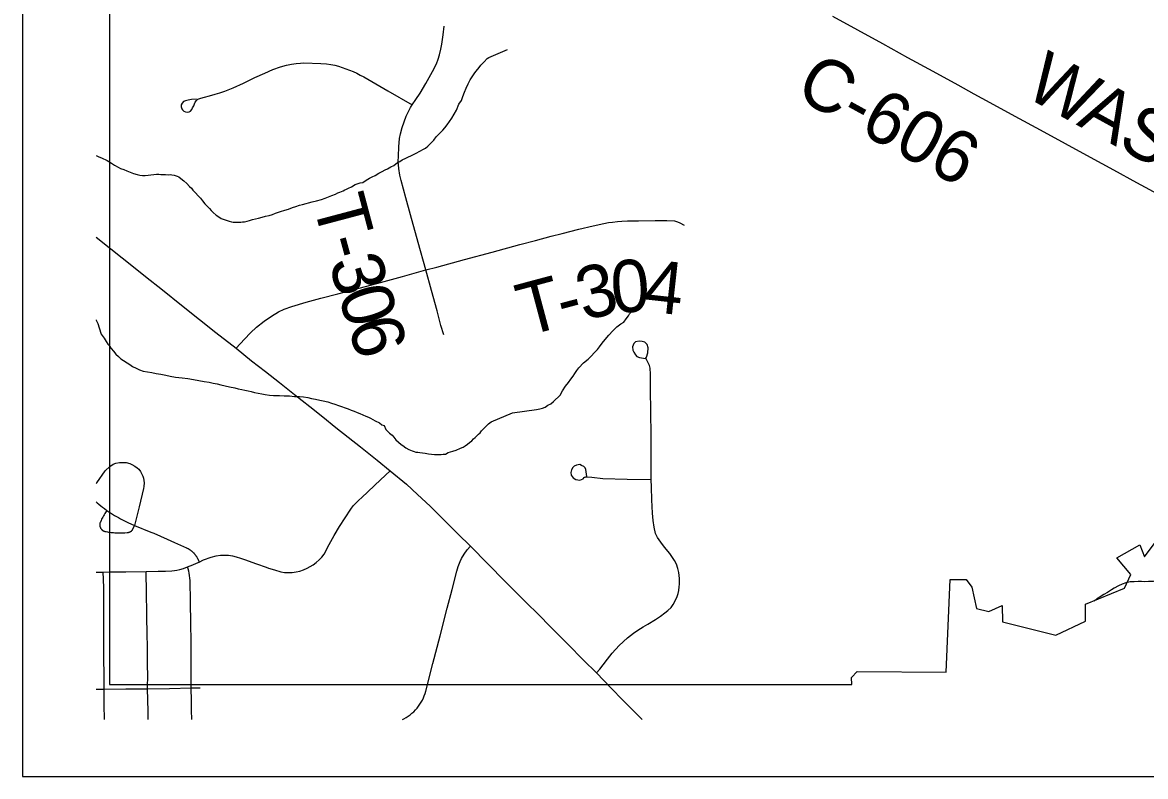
# Model space of a CAD drawing. Extents: x -11.4 to 84.1, y 11.1 to 59.
# Drawn here: x 26.165 to 27.387, y 40.548 to 41.368 of the extents above; entities that cross this region are included whole.
import ezdxf

# ---------------------------------------------------------------- set-up
doc = ezdxf.new("R2010")
doc.units = 0
for name, color, linetype in [('GM_X_Corporation', 7, 'Continuous'), ('GM_X_County_Road', 7, 'Continuous'), ('GM_X_County_Road_Text', 7, 'Continuous'), ('GM_X_Minor_River', 7, 'Continuous'), ('GM_X_Township_Road', 7, 'Continuous'), ('GM_X_Township_Road_Text', 7, 'Continuous'), ('SH_Data', 7, 'Continuous')]:
    doc.layers.add(name, color=color, linetype=linetype)

msp = doc.modelspace()

# ---------------------------------------------------------------- linework, layer by layer
at = {"layer": 'GM_X_Corporation'}
for points in [[(26.2599, 41.4853), (26.2599, 40.6483), (27.0672, 40.6483)], [(27.0672, 40.6483), (27.067, 40.6559), (27.0731, 40.6623), (27.1697, 40.6617), (27.1741, 40.7625), (27.1917, 40.7624), (27.1979, 40.754), (27.2027, 40.731), (27.2161, 40.7278), (27.2309, 40.7343), (27.2311, 40.7163), (27.2892, 40.702), (27.3213, 40.7172), (27.3213, 40.7356), (27.3639, 40.7528), (27.3708, 40.768), (27.3554, 40.7859), (27.3805, 40.7999), (27.3856, 40.7872), (27.4014, 40.8083)]]:
    msp.add_lwpolyline(points, dxfattribs=at)
at = {"layer": 'GM_X_County_Road'}
for points in [[(27.0462, 41.3747), (27.0735, 41.3597), (27.1007, 41.3448), (27.1279, 41.3298), (27.1552, 41.3149), (27.1824, 41.2999), (27.1999, 41.2903), (27.2174, 41.2807), (27.2446, 41.2659), (27.2719, 41.251), (27.2992, 41.2362), (27.3265, 41.2213), (27.3518, 41.2076), (27.377, 41.1938)], [(27.377, 41.1938), (27.4043, 41.179), (27.4259, 41.1672), (27.4474, 41.1555)], [(26.2454, 41.1344), (26.2615, 41.1216), (26.2859, 41.1023), (26.3009, 41.0904), (26.3159, 41.0785), (26.3402, 41.0592), (26.358, 41.045), (26.3757, 41.0308), (26.3976, 41.0137), (26.4143, 41.0002), (26.4295, 40.9884), (26.4447, 40.9766), (26.4612, 40.9635), (26.4777, 40.9505), (26.4919, 40.9391), (26.5061, 40.9277), (26.5195, 40.9171), (26.533, 40.9064), (26.551, 40.892), (26.565, 40.8805), (26.5831, 40.8659), (26.595, 40.8549), (26.6088, 40.842), (26.6238, 40.827), (26.6387, 40.812), (26.6525, 40.7986), (26.6714, 40.7795), (26.6902, 40.7604), (26.7016, 40.7489), (26.7131, 40.7375), (26.7264, 40.7242), (26.7396, 40.7109), (26.7583, 40.6921), (26.7754, 40.6749), (26.7894, 40.6609), (26.805, 40.6447), (26.8187, 40.631), (26.8325, 40.6172), (26.8394, 40.6103)]]:
    msp.add_lwpolyline(points, dxfattribs=at)
at = {"layer": 'GM_X_Minor_River'}
for points in [[(26.6479, 41.2965), (26.65, 41.3011), (26.6522, 41.3054), (26.6544, 41.3088), (26.6567, 41.3119), (26.6585, 41.3146), (26.6604, 41.3169), (26.6618, 41.3189), (26.6637, 41.3212), (26.6655, 41.3231), (26.6674, 41.3251), (26.6708, 41.3286), (26.6726, 41.3298), (26.6928, 41.3384)], [(26.3409, 41.1955), (26.344, 41.1929), (26.3471, 41.1895), (26.349, 41.1876), (26.3506, 41.1854), (26.3529, 41.1835), (26.3572, 41.1787), (26.3588, 41.1768), (26.3611, 41.1738), (26.3635, 41.1708), (26.3662, 41.1682), (26.3686, 41.1656), (26.3705, 41.1633), (26.3728, 41.1611), (26.3759, 41.1585), (26.379, 41.1566), (26.3814, 41.1548), (26.3837, 41.1541), (26.3856, 41.1533), (26.3879, 41.1526), (26.3902, 41.1519), (26.3925, 41.1512), (26.3944, 41.1509), (26.3967, 41.1509), (26.3986, 41.1506), (26.4005, 41.1506), (26.4028, 41.1506), (26.4047, 41.1511), (26.4066, 41.1511), (26.4096, 41.1519), (26.4123, 41.1527), (26.4153, 41.1536), (26.4187, 41.1544), (26.4221, 41.1552), (26.4259, 41.1561), (26.4297, 41.1573), (26.4335, 41.1581), (26.4372, 41.159), (26.4406, 41.1606), (26.4459, 41.1622), (26.4505, 41.1638), (26.4546, 41.165), (26.4588, 41.1666), (26.4626, 41.1679), (26.4664, 41.1691), (26.4698, 41.1699), (26.4804, 41.1728), (26.4849, 41.174), (26.4906, 41.1753), (26.4944, 41.1769), (26.4981, 41.1781), (26.5019, 41.1797), (26.5057, 41.1813), (26.5083, 41.1825), (26.5106, 41.1833), (26.514, 41.1849), (26.5159, 41.1857), (26.5178, 41.1865), (26.52, 41.1877), (26.523, 41.1893), (26.5272, 41.1916), (26.5325, 41.1933), (26.5355, 41.1937), (26.5392, 41.1964), (26.5426, 41.1984), (26.5456, 41.2), (26.5487, 41.2016), (26.5528, 41.204), (26.5566, 41.2059), (26.5599, 41.2075), (26.5622, 41.2087), (26.5641, 41.2099), (26.566, 41.2107), (26.569, 41.2123), (26.5731, 41.2154), (26.5757, 41.2166), (26.5784, 41.2186), (26.5821, 41.2202), (26.5851, 41.2217), (26.5878, 41.2229), (26.5904, 41.2241), (26.5927, 41.2253), (26.598, 41.2281), (26.6006, 41.2297), (26.6036, 41.2313), (26.6062, 41.2332), (26.6088, 41.2359), (26.6126, 41.2398), (26.6151, 41.2433), (26.6226, 41.2507), (26.6248, 41.2534), (26.627, 41.2565), (26.6296, 41.26), (26.6322, 41.2638), (26.6348, 41.2681), (26.6373, 41.2723), (26.6399, 41.2788), (26.6428, 41.2831), (26.6443, 41.2873), (26.6461, 41.2919), (26.6479, 41.2965)], [(26.2454, 41.2231), (26.2462, 41.2229), (26.2485, 41.2218), (26.2512, 41.2207), (26.2535, 41.2196), (26.2554, 41.2189), (26.2573, 41.2178), (26.2593, 41.2166), (26.262, 41.2148), (26.2654, 41.2126), (26.2693, 41.2104), (26.272, 41.2089), (26.2755, 41.2078), (26.2789, 41.2064), (26.2824, 41.2049), (26.2862, 41.2035), (26.29, 41.2024), (26.2931, 41.2017), (26.2958, 41.2014), (26.2988, 41.2015), (26.3019, 41.2019), (26.3049, 41.2023), (26.3083, 41.2024), (26.311, 41.2028), (26.3136, 41.2029), (26.3159, 41.2026), (26.3186, 41.2026), (26.3209, 41.2027), (26.3236, 41.2023), (26.3258, 41.2024), (26.3278, 41.202), (26.3301, 41.2017), (26.3335, 41.2006), (26.3354, 41.1999), (26.3377, 41.1981), (26.3409, 41.1955)], [(26.6984, 40.9436), (26.7245, 40.9473), (26.7279, 40.9477), (26.7309, 40.9485), (26.7339, 40.9497), (26.7365, 40.9517), (26.7399, 40.9532), (26.7429, 40.956), (26.75, 40.9629), (26.7526, 40.9675), (26.7559, 40.9725), (26.7593, 40.9764), (26.7615, 40.9802), (26.7641, 40.9833), (26.766, 40.9864), (26.7682, 40.9895), (26.7704, 40.9925), (26.7756, 40.9979), (26.7805, 41.0018), (26.7843, 41.0053), (26.7872, 41.0088), (26.7906, 41.0123), (26.7928, 41.0153), (26.7958, 41.0192), (26.7991, 41.0234), (26.8029, 41.028), (26.8073, 41.0327), (26.8118, 41.0369), (26.8159, 41.0404), (26.8193, 41.042), (26.8219, 41.0455), (26.8245, 41.0489), (26.8256, 41.0512), (26.8269, 41.0525)], [(26.2454, 41.0447), (26.2456, 41.0443), (26.2472, 41.0405), (26.2488, 41.0359), (26.2508, 41.0291), (26.254, 41.0246), (26.2564, 41.0209), (26.2583, 41.0182), (26.2603, 41.016), (26.2619, 41.0134), (26.2642, 41.0104), (26.2669, 41.0074), (26.2697, 41.0048), (26.2724, 41.0022), (26.282, 40.9959), (26.2851, 40.994), (26.289, 40.9922), (26.2925, 40.9904), (26.2967, 40.9889), (26.3013, 40.9879), (26.3059, 40.9872), (26.3108, 40.9862), (26.3158, 40.9855), (26.3211, 40.9845), (26.3261, 40.9835), (26.3319, 40.9824), (26.3391, 40.9814), (26.3452, 40.9808), (26.3513, 40.9798), (26.3571, 40.9788), (26.3628, 40.9777), (26.3682, 40.9767), (26.3728, 40.9756), (26.377, 40.975), (26.3812, 40.9739), (26.3858, 40.9729), (26.3904, 40.9718), (26.3961, 40.9708), (26.3999, 40.9697), (26.4038, 40.969), (26.4072, 40.9683), (26.4106, 40.9673), (26.4141, 40.9666), (26.4175, 40.9655), (26.4217, 40.9648), (26.4256, 40.9641), (26.4294, 40.9635), (26.434, 40.9628), (26.4382, 40.9625), (26.4447, 40.9623), (26.45, 40.962), (26.4557, 40.9621), (26.461, 40.9614), (26.4664, 40.9612), (26.471, 40.9609), (26.4755, 40.9602), (26.4798, 40.9592), (26.484, 40.9585), (26.4886, 40.9574), (26.4924, 40.9567), (26.4974, 40.9553), (26.5012, 40.9539), (26.505, 40.9528), (26.5089, 40.9514), (26.5196, 40.9478), (26.5227, 40.9463), (26.5261, 40.9453), (26.5292, 40.9438), (26.5323, 40.9427), (26.5354, 40.9412), (26.5388, 40.9398), (26.5415, 40.9387)], [(26.5415, 40.9387), (26.5438, 40.9376), (26.5465, 40.9361), (26.5488, 40.935), (26.5535, 40.9325), (26.5562, 40.9306), (26.5585, 40.9299), (26.5605, 40.9254), (26.5644, 40.9213), (26.5675, 40.9191), (26.569, 40.9172), (26.5714, 40.9142), (26.5772, 40.909), (26.5791, 40.9079), (26.5822, 40.9056), (26.5853, 40.9038), (26.5872, 40.9031), (26.5892, 40.9024), (26.5911, 40.9016), (26.593, 40.9009), (26.5953, 40.9006), (26.5976, 40.9003), (26.6003, 40.8999), (26.6033, 40.8996), (26.6068, 40.8989), (26.6102, 40.8986), (26.6133, 40.8983), (26.6159, 40.8983), (26.6186, 40.8984), (26.6205, 40.8984), (26.6228, 40.8985), (26.6254, 40.8985), (26.6284, 40.9005), (26.6334, 40.9017), (26.6371, 40.903), (26.6417, 40.905), (26.6447, 40.9062), (26.6469, 40.9077), (26.6492, 40.9093), (26.6514, 40.9112), (26.6541, 40.9132), (26.6559, 40.9151), (26.6578, 40.9167), (26.6611, 40.9202), (26.663, 40.9218), (26.6645, 40.9241), (26.6671, 40.9264), (26.6697, 40.9291), (26.6723, 40.9315), (26.6749, 40.9338), (26.6984, 40.9436)], [(27.4173, 40.7632), (27.4135, 40.7628), (27.409, 40.7619), (27.4014, 40.7607), (27.3953, 40.7602), (27.39, 40.7601), (27.3858, 40.76), (27.3824, 40.7604), (27.3786, 40.7603), (27.3744, 40.7599), (27.3699, 40.7598), (27.3653, 40.7589), (27.3612, 40.7574), (27.3574, 40.7554), (27.3525, 40.753), (27.3495, 40.7511), (27.3454, 40.7483), (27.3412, 40.746), (27.3375, 40.7437), (27.3341, 40.7417), (27.3322, 40.7401), (27.3303, 40.739), (27.3303, 40.739)]]:
    msp.add_lwpolyline(points, dxfattribs=at)
at = {"layer": 'GM_X_Township_Road'}
for points in [[(26.6235, 41.0283), (26.6204, 41.0386), (26.6163, 41.0542), (26.6101, 41.0765), (26.6039, 41.0989), (26.5956, 41.1288), (26.5873, 41.1588), (26.5822, 41.1773), (26.577, 41.1959), (26.5757, 41.2018), (26.5745, 41.2092), (26.5739, 41.2165), (26.5741, 41.2226), (26.5747, 41.2327), (26.5754, 41.2418), (26.5765, 41.2469), (26.5781, 41.2537), (26.5803, 41.2599), (26.5827, 41.2658), (26.5858, 41.2726), (26.5874, 41.2755), (26.5891, 41.2782), (26.5932, 41.2842), (26.5978, 41.2909), (26.6039, 41.3013), (26.6113, 41.3146), (26.6155, 41.3229), (26.6174, 41.3279), (26.6189, 41.3325), (26.6204, 41.3389), (26.6212, 41.344), (26.6227, 41.3543), (26.6238, 41.3638)], [(26.3547, 41.2843), (26.3493, 41.2839), (26.3456, 41.2834), (26.3427, 41.2826), (26.3405, 41.2817), (26.3388, 41.2802), (26.338, 41.2782), (26.3379, 41.2761), (26.3385, 41.274), (26.3393, 41.2728), (26.3408, 41.2714), (26.3427, 41.2705), (26.3449, 41.2704), (26.3467, 41.2706), (26.348, 41.2714), (26.3496, 41.2732), (26.3503, 41.275), (26.3515, 41.2772), (26.3523, 41.2793), (26.3532, 41.2811), (26.3545, 41.2831), (26.3561, 41.2844), (26.3591, 41.2855), (26.3632, 41.2864), (26.3686, 41.2879), (26.3747, 41.2899), (26.3798, 41.2914), (26.3852, 41.2932), (26.3944, 41.2968), (26.4057, 41.3017), (26.4181, 41.308), (26.4287, 41.3128), (26.4376, 41.3167), (26.446, 41.3194), (26.4526, 41.3212), (26.4579, 41.3224), (26.4631, 41.3232), (26.4676, 41.3235), (26.4714, 41.3238), (26.4897, 41.3233), (26.4961, 41.3229), (26.5008, 41.3221), (26.5049, 41.3212), (26.509, 41.3201), (26.5131, 41.3188), (26.5171, 41.3175), (26.5211, 41.3159), (26.5251, 41.3143), (26.5289, 41.3125), (26.5327, 41.3106), (26.5364, 41.3085), (26.5627, 41.2934), (26.5891, 41.2782)], [(26.3976, 41.0137), (26.4067, 41.0236), (26.4132, 41.0303), (26.4197, 41.0366), (26.4281, 41.0433), (26.4361, 41.0486), (26.4437, 41.0533), (26.45, 41.0562), (26.4582, 41.0591), (26.4739, 41.0637), (26.4896, 41.0683), (26.5082, 41.073), (26.5261, 41.0774), (26.5508, 41.0841), (26.5787, 41.0916), (26.6039, 41.0989), (26.6161, 41.102), (26.6461, 41.1101), (26.6761, 41.1182), (26.7061, 41.1263), (26.7231, 41.1308), (26.7401, 41.1354), (26.7522, 41.1385), (26.7704, 41.1432), (26.7861, 41.1468), (26.7975, 41.1494), (26.8027, 41.1502), (26.8071, 41.1509), (26.8123, 41.1515), (26.8173, 41.1517), (26.8233, 41.152), (26.8354, 41.1521), (26.8532, 41.1524), (26.8659, 41.1525), (26.8743, 41.152), (26.8776, 41.1512), (26.8803, 41.15), (26.8849, 41.1476)], [(26.7894, 40.6609), (26.7931, 40.6651), (26.7968, 40.6697), (26.8015, 40.6759), (26.8065, 40.6825), (26.8141, 40.6908), (26.8234, 40.6991), (26.8298, 40.7039), (26.8345, 40.7073), (26.8403, 40.7109), (26.8455, 40.7139), (26.8539, 40.7189), (26.8593, 40.7226), (26.864, 40.7262), (26.8672, 40.7288), (26.8706, 40.7319), (26.873, 40.7354), (26.8753, 40.7392), (26.8772, 40.7438), (26.8784, 40.7473), (26.8791, 40.7506), (26.8795, 40.7545), (26.8798, 40.7574), (26.8799, 40.7636), (26.8791, 40.77), (26.8782, 40.7742), (26.8765, 40.7789), (26.8744, 40.783), (26.8692, 40.7905), (26.8636, 40.7975), (26.8594, 40.803), (26.8559, 40.808), (26.8539, 40.8125), (26.8522, 40.8194), (26.8511, 40.8265), (26.8503, 40.8345), (26.8497, 40.8489), (26.8494, 40.8628), (26.8491, 40.871), (26.8491, 40.8937), (26.849, 40.9163), (26.8486, 40.9474), (26.8484, 40.9665), (26.8482, 40.9857), (26.8478, 40.9921), (26.8473, 40.9948), (26.8463, 40.9971), (26.8451, 40.9994), (26.844, 41.0015), (26.8436, 41.0022), (26.8435, 41.0025), (26.8434, 41.0028), (26.8438, 41.0041), (26.8453, 41.0086), (26.8458, 41.0141), (26.8445, 41.0179), (26.842, 41.0203), (26.8393, 41.0211), (26.8358, 41.0214), (26.8321, 41.0207), (26.8301, 41.0187), (26.8288, 41.0151), (26.8292, 41.0118), (26.8302, 41.0093), (26.8319, 41.0065), (26.8336, 41.0048), (26.8363, 41.0035), (26.8428, 41.0024)], [(26.2454, 40.8666), (26.2461, 40.8676), (26.2554, 40.8804), (26.2602, 40.8853), (26.2641, 40.8876), (26.2667, 40.8887), (26.2707, 40.8894), (26.2744, 40.8896), (26.278, 40.8894), (26.2819, 40.8884), (26.2844, 40.8874), (26.2874, 40.8857), (26.2899, 40.8839), (26.292, 40.8822), (26.2938, 40.8797), (26.2948, 40.8776), (26.2961, 40.8746), (26.2968, 40.8726), (26.2976, 40.8675), (26.2974, 40.8636), (26.297, 40.8612), (26.2921, 40.8412), (26.2872, 40.8212)], [(26.2454, 40.7705), (26.2531, 40.7705), (26.2601, 40.7706), (26.2681, 40.7708), (26.2778, 40.7709), (26.2998, 40.7711), (26.3129, 40.7713), (26.3209, 40.7715), (26.3276, 40.7719), (26.3306, 40.7722), (26.3333, 40.7727), (26.3364, 40.7733), (26.3406, 40.7745), (26.3448, 40.7761), (26.3477, 40.7772), (26.3505, 40.7784), (26.3544, 40.78), (26.3573, 40.7814), (26.3621, 40.7836), (26.3705, 40.7865), (26.3759, 40.788), (26.3805, 40.7887), (26.3849, 40.7889), (26.3894, 40.7887), (26.3937, 40.788), (26.3978, 40.7871), (26.4025, 40.7857), (26.4067, 40.7841), (26.4198, 40.7793), (26.4303, 40.7757), (26.4329, 40.7748), (26.4393, 40.7728), (26.4461, 40.7706), (26.4503, 40.7701), (26.4545, 40.7699), (26.4586, 40.7701), (26.4628, 40.7707), (26.4669, 40.7716), (26.4709, 40.7729), (26.4749, 40.7746), (26.4783, 40.7764), (26.4816, 40.7785), (26.4848, 40.7809), (26.4878, 40.7837), (26.4907, 40.7868), (26.4934, 40.7901), (26.4988, 40.8003), (26.5044, 40.8102), (26.5102, 40.8199), (26.5161, 40.8294), (26.5223, 40.8387), (26.5251, 40.8423), (26.5281, 40.8456), (26.5312, 40.8487), (26.5344, 40.8516), (26.5548, 40.8708), (26.565, 40.8805)], [(26.779, 40.8745), (26.7779, 40.8818), (26.7771, 40.8837), (26.7757, 40.8851), (26.7733, 40.8864), (26.7713, 40.8874), (26.7679, 40.8868), (26.7653, 40.8855), (26.764, 40.8841), (26.7624, 40.8814), (26.7618, 40.8788), (26.762, 40.8757), (26.7642, 40.8728), (26.7671, 40.871), (26.7713, 40.8705), (26.7732, 40.871), (26.7749, 40.8718), (26.7761, 40.8731), (26.7767, 40.8735), (26.7774, 40.8737), (26.7779, 40.8738), (26.7845, 40.8737), (26.7964, 40.872), (26.8228, 40.8715), (26.8491, 40.871)], [(26.2454, 40.8469), (26.2466, 40.8458), (26.2485, 40.8442), (26.2505, 40.8426), (26.2524, 40.8411), (26.2544, 40.8396), (26.2572, 40.8375), (26.2592, 40.8361), (26.2612, 40.8348), (26.2633, 40.8334), (26.2654, 40.8321), (26.2675, 40.8308), (26.2697, 40.8296), (26.2719, 40.8284), (26.2741, 40.8272), (26.2762, 40.8261), (26.2785, 40.825), (26.2807, 40.824), (26.283, 40.8229), (26.2872, 40.8212), (26.3049, 40.814), (26.3082, 40.8126), (26.3153, 40.8095), (26.3227, 40.8061), (26.3306, 40.8026), (26.3437, 40.7968), (26.3442, 40.7966), (26.3445, 40.7964), (26.345, 40.7962), (26.3454, 40.796), (26.3457, 40.7957), (26.3462, 40.7955), (26.3465, 40.7953), (26.3469, 40.795), (26.3473, 40.7948), (26.3477, 40.7945), (26.3481, 40.7943), (26.3484, 40.794), (26.3488, 40.7937), (26.3491, 40.7934), (26.3495, 40.7931), (26.3498, 40.7928), (26.3501, 40.7925), (26.3505, 40.7922), (26.3508, 40.7919), (26.3511, 40.7916), (26.3515, 40.7913), (26.3518, 40.7909), (26.3521, 40.7906), (26.3524, 40.7902), (26.3527, 40.7899), (26.3529, 40.7895), (26.3532, 40.7892), (26.3535, 40.7888), (26.3538, 40.7884), (26.354, 40.7881), (26.3543, 40.7877), (26.3545, 40.7873), (26.3548, 40.7869), (26.355, 40.7866), (26.3553, 40.7861), (26.3554, 40.7858), (26.3557, 40.7854), (26.3559, 40.7849), (26.3561, 40.7846), (26.3563, 40.7841), (26.3565, 40.7837), (26.3566, 40.7833), (26.3568, 40.7829), (26.357, 40.7825), (26.3572, 40.782), (26.3573, 40.7814)], [(26.2572, 40.8375), (26.2564, 40.8364), (26.2556, 40.8352), (26.2548, 40.834), (26.2541, 40.8328), (26.2534, 40.8315), (26.2527, 40.8303), (26.2521, 40.829), (26.2514, 40.8278), (26.2508, 40.8265), (26.25, 40.8246), (26.2499, 40.8245), (26.2499, 40.8244), (26.2498, 40.8243), (26.2498, 40.8242), (26.2497, 40.824), (26.2497, 40.8239), (26.2496, 40.8238), (26.2496, 40.8237), (26.2496, 40.8236), (26.2495, 40.8234), (26.2495, 40.8233), (26.2495, 40.8232), (26.2495, 40.8231), (26.2494, 40.8229), (26.2494, 40.8228), (26.2494, 40.8227), (26.2494, 40.8226), (26.2494, 40.8224), (26.2493, 40.8223), (26.2493, 40.8222), (26.2493, 40.8221), (26.2493, 40.822), (26.2493, 40.8218), (26.2493, 40.8217), (26.2493, 40.8216), (26.2493, 40.8214), (26.2493, 40.8213), (26.2493, 40.8212), (26.2494, 40.8211), (26.2494, 40.8209), (26.2494, 40.8208), (26.2494, 40.8207), (26.2494, 40.8206), (26.2494, 40.8204), (26.2495, 40.8203), (26.2495, 40.8202), (26.2495, 40.8201), (26.2496, 40.82), (26.2496, 40.8198), (26.2496, 40.8197), (26.2497, 40.8196), (26.2497, 40.8195), (26.2497, 40.8193), (26.2498, 40.8192), (26.2498, 40.8191), (26.2499, 40.819), (26.2499, 40.8189), (26.25, 40.8188), (26.25, 40.8187), (26.25, 40.8185), (26.2501, 40.8184), (26.2502, 40.8183), (26.2502, 40.8182), (26.2503, 40.8181), (26.2504, 40.818), (26.2504, 40.8179), (26.2505, 40.8178), (26.2506, 40.8177), (26.2507, 40.8176), (26.2507, 40.8175), (26.2508, 40.8174), (26.2508, 40.8173), (26.2509, 40.8172), (26.251, 40.8171), (26.2511, 40.817), (26.2512, 40.8169), (26.2513, 40.8168), (26.2514, 40.8167), (26.2515, 40.8166), (26.2516, 40.8165), (26.2517, 40.8164), (26.2517, 40.8163), (26.2518, 40.8163), (26.2519, 40.8162), (26.252, 40.8161), (26.2521, 40.816), (26.2522, 40.8159), (26.2523, 40.8159), (26.2524, 40.8158), (26.2525, 40.8157), (26.2526, 40.8157), (26.2527, 40.8156), (26.2528, 40.8155), (26.2529, 40.8155), (26.2531, 40.8154), (26.2532, 40.8153), (26.2533, 40.8153), (26.2534, 40.8152), (26.2535, 40.8152), (26.2536, 40.8151), (26.2537, 40.8151), (26.2538, 40.815), (26.254, 40.815), (26.2541, 40.8149), (26.2542, 40.8149), (26.2543, 40.8149), (26.2545, 40.8148), (26.2545, 40.8148), (26.2547, 40.8147), (26.2548, 40.8147), (26.255, 40.8147), (26.2563, 40.8144), (26.2577, 40.8142), (26.259, 40.8139), (26.2604, 40.8137), (26.2617, 40.8136), (26.263, 40.8134), (26.2644, 40.8133), (26.2657, 40.8132), (26.2671, 40.8131), (26.2684, 40.813), (26.2698, 40.813), (26.2712, 40.813), (26.2725, 40.813), (26.2739, 40.813), (26.2752, 40.8131), (26.2766, 40.8132), (26.2792, 40.8134), (26.2793, 40.8134), (26.2795, 40.8134), (26.2797, 40.8134), (26.2798, 40.8135), (26.2799, 40.8135), (26.2801, 40.8135), (26.2803, 40.8136), (26.2804, 40.8136), (26.2806, 40.8136), (26.2807, 40.8137), (26.2809, 40.8137), (26.281, 40.8138), (26.2812, 40.8138), (26.2813, 40.8139), (26.2815, 40.8139), (26.2816, 40.814), (26.2818, 40.814), (26.2819, 40.8141), (26.2821, 40.8142), (26.2822, 40.8142), (26.2824, 40.8143), (26.2825, 40.8144), (26.2826, 40.8145), (26.2828, 40.8145), (26.2829, 40.8146), (26.283, 40.8147), (26.2832, 40.8148), (26.2833, 40.8149), (26.2834, 40.815), (26.2836, 40.8151), (26.2837, 40.8151), (26.2838, 40.8152), (26.284, 40.8154), (26.2841, 40.8154), (26.2842, 40.8156), (26.2843, 40.8157), (26.2844, 40.8158), (26.2845, 40.8159), (26.2847, 40.816), (26.2848, 40.8161), (26.2849, 40.8162), (26.285, 40.8163), (26.2851, 40.8165), (26.2872, 40.8212)], [(26.5785, 40.6103), (26.5802, 40.6111), (26.5825, 40.6124), (26.5847, 40.6138), (26.5869, 40.6153), (26.5889, 40.617), (26.5908, 40.6187), (26.5927, 40.6206), (26.5944, 40.6226), (26.596, 40.6246), (26.5975, 40.6268), (26.5989, 40.629), (26.6002, 40.6313), (26.6013, 40.6337), (26.6023, 40.6361), (26.6032, 40.6386), (26.6039, 40.6411), (26.6117, 40.6712), (26.6195, 40.7012), (26.6273, 40.7313), (26.6325, 40.7514), (26.6377, 40.7715), (26.6384, 40.774), (26.6392, 40.7764), (26.6412, 40.7818), (26.6429, 40.7852), (26.6458, 40.7901), (26.6491, 40.7947), (26.6525, 40.7986)], [(26.2544, 40.6103), (26.2543, 40.6263), (26.2541, 40.6433), (26.254, 40.6596), (26.2539, 40.676), (26.2538, 40.6906), (26.2536, 40.7529), (26.2533, 40.7627), (26.2531, 40.7705)], [(26.3021, 40.6103), (26.302, 40.6193), (26.3014, 40.6437), (26.3015, 40.6596), (26.3014, 40.6679), (26.3011, 40.6867), (26.3008, 40.7056), (26.3006, 40.7195), (26.3005, 40.7297), (26.3003, 40.7435), (26.3001, 40.7553), (26.3, 40.7636), (26.2998, 40.7711)], [(26.3488, 40.6446), (26.3489, 40.6553), (26.3488, 40.681), (26.3486, 40.695), (26.3483, 40.7147), (26.348, 40.738), (26.3476, 40.7614), (26.3474, 40.7639), (26.3471, 40.7668), (26.3466, 40.7693), (26.3462, 40.7715), (26.3454, 40.7739), (26.3448, 40.7761)], [(26.2454, 40.6431), (26.2457, 40.6431), (26.2541, 40.6433), (26.2778, 40.6435), (26.3014, 40.6437), (26.3251, 40.6441)], [(26.3251, 40.6441), (26.3488, 40.6446), (26.3586, 40.6447)], [(26.3494, 40.6103), (26.3493, 40.6205), (26.3492, 40.6307), (26.3488, 40.6446)]]:
    msp.add_lwpolyline(points, dxfattribs=at)
at = {"layer": 'SH_Data'}
for p, q in [((26.1653, 47.5483), (26.1653, 40.5483)), ((26.1653, 40.5483), (33.1653, 40.5483))]:
    msp.add_line(p, q, dxfattribs=at)

# ---------------------------------------------------------------- texts
at = {"layer": 'GM_X_County_Road_Text'}
for s, height, rotation, p in [('W', 0.0568, 331.227, (27.2529, 41.2887)), ('C-606', 0.05682, 331.2136, (27.0035, 41.2877)), ('A', 0.0568, 331.2253, (27.3106, 41.257)), ('S', 0.0568, 331.2255, (27.3544, 41.233))]:
    msp.add_text(s, height=height, rotation=rotation, dxfattribs=at).set_placement(p)
at = {"layer": 'GM_X_Township_Road_Text'}
for s, rotation, p in [('T', 284.8751, (26.4807, 41.1723)), ('-', 285.2686, (26.4917, 41.1308)), ('3', 286.0428, (26.4981, 41.1075)), ('3', 14.3568, (26.7758, 41.0434)), ('0', 4.099, (26.807, 41.0516)), ('4', 353.7426, (26.8392, 41.0542)), ('T', 14.9593, (26.7123, 41.0265)), ('0', 286.9208, (26.508, 41.073)), ('-', 14.8977, (26.7534, 41.0374)), ('6', 287.4821, (26.5184, 41.0389))]:
    msp.add_text(s, height=0.0568, rotation=rotation, dxfattribs=at).set_placement(p)

doc.saveas('drawing.dxf')
